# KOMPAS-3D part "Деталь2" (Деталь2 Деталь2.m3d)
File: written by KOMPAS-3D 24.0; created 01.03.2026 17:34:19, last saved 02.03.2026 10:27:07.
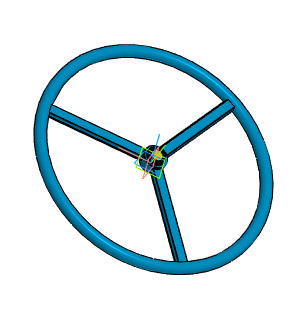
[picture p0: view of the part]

Document properties: Автор: R2D2; Полное имя файла: E:\Работа\Зайцев\GVWR3131M-2W-F-S Задвижка клиновая с выдвижным штоком DN.ru Ду50-200 Ру63\DN200\исходные материалы\Деталь2 Деталь2.m3d

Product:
- Body: Твердое тело1  | qty 1
    Масса: 7.825268
- Part/product: Деталь2
    Масса: 7.825268
    additional columns: Типовые

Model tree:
1. Твердое тело1  (labels: Твердое тело1)
2. Эскиз:1
3. Элемент выдавливания:1
     Расстояние 1 = 100
4. Эскиз:2
5. Элемент вращения:1
     Угол 1 = 360
6. Элемент выдавливания:2  (with: Грань.Элемент выдавливания:1, Грань.Элемент вращения:1)
     Расстояние 2 = 167.966
7. Массив по концентрической сетке:1  (with: Элемент выдавливания:2)  (labels: Грань.Твердое тело1)  (3 pattern instances)
     Шаг 2 = 360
